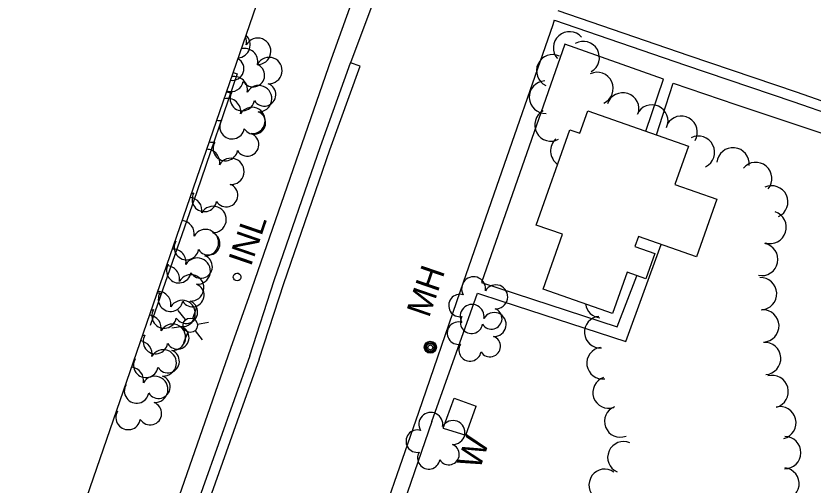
# Model space of a CAD drawing. Extents: x 189384 to 193282, y 256970 to 260388.
# Drawn here: x 190383.3 to 190581.3, y 258710.5 to 258826.9 of the extents above; entities that cross this region are included whole.
import ezdxf

# ---------------------------------------------------------------- set-up
doc = ezdxf.new("R2010")
doc.units = 0
for name, color, linetype in [('E_DRN_Grate', 7, 'Continuous'), ('E_DWY', 7, 'Continuous'), ('E_LAND_Vegetation', 7, 'Continuous'), ('E_MAP_Limits', 7, 'Continuous'), ('E_MISCPROP', 7, 'Continuous'), ('E_MISCPROP_HvyLine', 7, 'Continuous'), ('E_MISCPROP_Railing', 7, 'Continuous'), ('E_PATH_Sidewalk', 7, 'Continuous'), ('E_RDWY', 7, 'Continuous')]:
    doc.layers.add(name, color=color, linetype=linetype)

# ---------------------------------------------------------------- blocks, each defined once
blk = doc.blocks.new('INL_2')
at = {"layer": 'E_MISCPROP_Railing'}
blk.add_text('INL', height=6, rotation=359.9999, dxfattribs=at).set_placement((-5.79, -2.75))
blk = doc.blocks.new('LTP_12')
at = {"layer": 'E_MISCPROP'}
for p, q in [((-0.88, 1.57), (-2.2, 4.11)), ((0.99, 1.56), (2.49, 4.02)), ((-1.8, 0.07), (-4.66, 0.15)), ((-0.96, -1.57), (-2.46, -3.98)), ((0.83, -1.62), (2.2, -4.01)), ((1.8, -0.03), (4.58, -0.1))]:
    blk.add_line(p, q, dxfattribs=at)
blk.add_circle((0, 0), 1.8, dxfattribs=at)
blk = doc.blocks.new('MHO_5')
at = {"layer": 'E_DRN_Grate'}
for centre, radius in [((0.04, -0.06), 1.5), ((0.04, -0.06), 1.22), ((0.04, -0.07), 0.968), ((0.01, -0.08), 0.605)]:
    blk.add_circle(centre, radius, dxfattribs=at)
blk = doc.blocks.new('WAL_7')
at = {"layer": 'E_MISCPROP_Railing'}
blk.add_text('W', height=6, rotation=0.0001, dxfattribs=at).set_placement((-2.27, -3.34))
blk = doc.blocks.new('TREE_11')
at = {"layer": 'E_LAND_Vegetation'}
for centre, radius, start, end in [((-1.47, 4.28), 2.78, 1.3946, 209.1676), ((3.57, 2.42), 2.97, 278.4237, 139.6576), ((-4.47, 0.2), 2.78, 78.0716, 279.0827), ((3.46, -3.43), 2.97, 196.0745, 79.0478), ((-2.01, -4.2), 2.61, 140.7798, 358.7124)]:
    blk.add_arc(centre, radius, start, end, dxfattribs=at)

msp = doc.modelspace()

# ---------------------------------------------------------------- linework, layer by layer
at = {"layer": 'E_DWY'}
msp.add_lwpolyline([(190437.28, 258812.87), (190438.3, 258812.51), (190428.25, 258783.25), (190416.64, 258750.06)], dxfattribs=at)
at = {"layer": 'E_LAND_Vegetation'}
for centre, radius, start, end in [((190438.25, 258819.76), 3.27, 274.9201, 47.0406), ((190437.34, 258820.36), 3.27, 349.4611, 24.2947), ((190443.39, 258818.15), 3.27, 267.1119, 150.0852), ((190520.83, 258818.98), 4.02, 41.5431, 221.5278), ((190524.24, 258816.6), 4.02, 299.2194, 119.2041), ((190440.13, 258815.58), 3.27, 349.4611, 104.6274), ((190516.66, 258813.31), 4.02, 64.5499, 244.5346), ((190437.09, 258813.8), 2.87, 260.6064, 61.3543), ((190446.18, 258813.37), 3.27, 267.1119, 150.0852), ((190442.23, 258812.19), 2.87, 211.8171, 69.7497), ((190437.59, 258808.6), 3.27, 349.4611, 102.0227), ((190527.66, 258808.92), 4.02, 294.5945, 114.5792), ((190436.78, 258811.2), 3.06, 249.6819, 350.12), ((190443.64, 258806.39), 3.27, 267.1119, 150.0852), ((190445.02, 258807.41), 2.87, 211.8171, 69.7497), ((190514.84, 258806.76), 4.02, 92.4972, 272.4819), ((190436.39, 258811), 3.05, 255.2097, 280.205), ((190439.56, 258806.42), 3.06, 149.109, 350.12), ((190534.07, 258803.84), 4.02, 341.8243, 161.809), ((190435.91, 258803.18), 3.27, 349.4611, 105.8454), ((190441.96, 258800.97), 3.27, 267.1119, 150.0852), ((190516.21, 258799.85), 4.02, 118.6237, 298.6084), ((190541.28, 258800.84), 4.02, 336.0452, 156.0299), ((190442.48, 258800.43), 2.87, 211.8171, 69.7497), ((190548.56, 258798.04), 4.02, 329.8882, 149.8729), ((190433.85, 258804.02), 3.05, 257.5768, 280.205), ((190437.02, 258799.44), 3.06, 149.109, 350.12), ((190440.8, 258795.01), 2.87, 211.8171, 69.7497), ((190432.18, 258798.6), 3.05, 254.1293, 280.205), ((190435.35, 258794.02), 3.06, 149.109, 350.12), ((190520.14, 258793.43), 4.02, 132.1523, 235.6774), ((190552.84, 258793.08), 4.02, 296.6675, 116.6522), ((190430.69, 258790.56), 3.27, 349.4611, 89.6597), ((190561.45, 258790.2), 4.02, 354.508, 174.4927), ((190436.74, 258788.35), 3.27, 267.1119, 150.0852), ((190567.1, 258786.57), 4.02, 320.161, 140.1457), ((190435.59, 258782.39), 2.87, 211.8171, 69.7497), ((190571.06, 258780.75), 4.02, 295.2791, 115.2638), ((190426.26, 258778.62), 3.27, 349.4611, 84.1682), ((190426.96, 258785.98), 3.05, 269.8933, 280.205), ((190430.13, 258781.4), 3.06, 149.109, 350.12), ((190432.31, 258776.41), 3.27, 267.1119, 150.0852), ((190570.67, 258774.45), 4.02, 252.3944, 72.3791), ((190424.36, 258772.86), 3.27, 349.4611, 85.5461), ((190430.41, 258770.66), 3.27, 267.1119, 150.0852), ((190431.15, 258770.45), 2.87, 211.8171, 69.7497), ((190425.69, 258769.46), 3.06, 149.109, 350.12), ((190422.52, 258774.03), 3.05, 275.9913, 280.205), ((190568.57, 258766.48), 4.02, 258.3214, 78.306), ((190422.31, 258765.79), 3.27, 349.4611, 92.3949), ((190428.36, 258763.58), 3.27, 267.1119, 150.0852), ((190429.25, 258764.69), 2.87, 211.8171, 69.7497), ((190423.79, 258763.7), 3.06, 149.109, 350.12), ((190420.71, 258761.63), 3.27, 349.4611, 89.5112), ((190420.62, 258768.28), 3.05, 274.4204, 280.205), ((190426.76, 258759.42), 3.27, 267.1119, 150.0852), ((190568.28, 258757.98), 4.02, 272.7769, 92.7616), ((190427.2, 258757.62), 2.87, 211.8171, 69.7497), ((190418.58, 258761.21), 3.05, 267.0086, 280.205), ((190418.57, 258755.28), 3.27, 349.4611, 90.2751), ((190421.75, 258756.63), 3.06, 149.109, 350.12), ((190424.62, 258753.07), 3.27, 267.1119, 150.0852), ((190425.6, 258753.46), 2.87, 211.8171, 69.7497), ((190416.98, 258757.05), 3.05, 270.0528, 280.205), ((190420.15, 258752.47), 3.06, 149.109, 350.12), ((190528.69, 258755.94), 3.92, 187.4333, 265.8223), ((190568.85, 258749.99), 4.02, 272.1291, 92.1138), ((190416.17, 258749.38), 3.27, 349.4611, 84.0272), ((190528.45, 258748.44), 3.92, 94.5735, 274.5582), ((190422.22, 258747.17), 3.27, 267.1119, 150.0852), ((190423.46, 258747.1), 2.87, 211.8171, 69.7497), ((190413.87, 258743.02), 3.27, 349.4611, 82.2034), ((190414.83, 258750.69), 3.05, 269.2359, 280.205), ((190418, 258746.12), 3.06, 149.109, 350.12), ((190569.3, 258741.9), 4.02, 274.0311, 94.0158), ((190419.92, 258740.81), 3.27, 267.1119, 150.0852), ((190421.06, 258741.2), 2.87, 211.8171, 69.7497), ((190529.05, 258740.74), 3.92, 98.0905, 278.0752), ((190415.6, 258740.22), 3.06, 149.109, 350.12), ((190412.44, 258744.79), 3.05, 276.1537, 280.205), ((190411.77, 258736.45), 3.27, 349.4611, 85.0277), ((190417.82, 258734.24), 3.27, 267.1119, 150.0852), ((190418.76, 258734.85), 2.87, 211.8171, 69.7497), ((190530.54, 258733.47), 3.92, 108.8594, 288.8441), ((190571.16, 258733.69), 4.02, 285.353, 105.3377), ((190413.31, 258733.86), 3.06, 149.109, 350.12), ((190410.14, 258738.44), 3.05, 278.2825, 280.205), ((190416.66, 258728.28), 2.87, 211.8171, 69.7497), ((190411.21, 258727.29), 3.06, 149.109, 350.12), ((190408.04, 258731.87), 3.05, 275.0081, 280.205), ((190533.45, 258726.29), 3.92, 111.3205, 291.3052), ((190573.1, 258725.95), 4.02, 283.8724, 103.8571), ((190574.29, 258718.55), 4.02, 269.204, 89.1886), ((190534.23, 258717.35), 3.92, 65.9456, 245.9303), ((190529.59, 258710.54), 3.92, 54.3628, 234.3475), ((190573.85, 258710.77), 4.02, 263.041, 83.0257)]:
    msp.add_arc(centre, radius, start, end, dxfattribs=at)
at = {"layer": 'E_MAP_Limits'}
msp.add_lwpolyline([(190400.94, 258707.45), (190457.96, 258872.88)], dxfattribs=at)
at = {"layer": 'E_MISCPROP_HvyLine'}
msp.add_lwpolyline([(190525.39, 258803.4), (190550.36, 258794.62), (190547, 258785.08), (190557.4, 258781.43), (190552.38, 258767.14), (190537.94, 258772.21), (190537.07, 258769.72), (190542.02, 258767.98), (190539.8, 258761.64), (190535.12, 258763.29), (190531.53, 258753.07), (190514.33, 258759.12), (190519.11, 258772.72), (190512.57, 258775.02), (190520.89, 258798.68), (190523.42, 258797.79)], close=True, dxfattribs=at)
at = {"layer": 'E_MISCPROP_Railing'}
for points in [[(190489.49, 258724.63), (190492.16, 258732.03), (190497.68, 258730.04)], [(190489.49, 258724.63), (190495.08, 258722.85), (190497.68, 258730.04)]]:
    msp.add_lwpolyline(points, dxfattribs=at)
msp.add_ellipse((190438.27, 258762.13), major_axis=(-0.908, 0.299), ratio=0.999792, dxfattribs=at)
at = {"layer": 'E_PATH_Sidewalk'}
for points in [[(190447.18, 258841.59), (190468.1, 258834.24), (190461.64, 258816.22), (190441.14, 258757.22), (190436.59, 258744.35), (190421.31, 258700.47)], [(190539.82, 258798.33), (190544.16, 258811.25), (190544.15, 258811.23), (190519.66, 258819.88), (190498.95, 258760.8), (190532.71, 258749.79), (190537.54, 258762.44)], [(190542.43, 258797.41), (190544.72, 258804.59), (190546.6, 258810.25), (190562.16, 258804.98), (190584.72, 258797.43)], [(190486.64, 258726.28), (190497.97, 258758.11), (190504.03, 258756.15), (190534.79, 258746.1), (190543.64, 258770.21)], [(190486.64, 258726.28), (190473.61, 258688.57)]]:
    msp.add_lwpolyline(points, dxfattribs=at)
at = {"layer": 'E_RDWY'}
for points in [[(190450.5, 258851.22), (190472.19, 258843.7), (190474.02, 258842.86), (190474.53, 258842.35), (190474.82, 258841.87), (190474.94, 258841.39), (190475.31, 258840.22), (190475.32, 258839.68), (190475.2, 258839.12), (190472.95, 258832.78), (190466.45, 258815.28)], [(190517.92, 258828.27), (190550.43, 258817.07), (190577.1, 258808.05), (190598.18, 258800.75), (190616.38, 258794.51), (190642.44, 258785.51), (190649.41, 258783.07), (190686.16, 258770.53), (190696.24, 258766.91)], [(190470.58, 258691.68), (190483.37, 258728.62), (190493.78, 258758.71), (190502.09, 258782.76), (190516.78, 258824.81), (190517.11, 258825.92)], [(190517.1, 258825.9), (190549.63, 258814.7), (190576.29, 258805.69), (190597.36, 258798.39), (190615.57, 258792.15), (190641.62, 258783.15), (190648.59, 258780.71), (190685.33, 258768.17), (190695.4, 258764.56)], [(190441.39, 258742.52), (190447.47, 258761.28), (190458.96, 258794.54), (190466.45, 258815.28)], [(190443.77, 258741.74), (190449.84, 258760.48), (190461.31, 258793.7), (190468.8, 258814.43), (190466.45, 258815.28)], [(190441.39, 258742.52), (190425.87, 258698.91), (190422.78, 258690.21), (190396.55, 258614.58), (190383.33, 258576.48)], [(190443.77, 258741.74), (190428.24, 258698.1), (190425.13, 258689.38), (190398.92, 258613.76), (190385.7, 258575.66), (190383.33, 258576.48)]]:
    msp.add_lwpolyline(points, dxfattribs=at)

# ---------------------------------------------------------------- block references
at = {"layer": 'E_DRN_Grate', "rotation": 71.0373537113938}
msp.add_blockref('MHO_5', (190486.19, 258744.67), dxfattribs=at)
at = {"layer": 'E_LAND_Vegetation'}
for p, rotation in [((190498.14, 258755.05), 71.03735349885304), ((190497.76, 258748.18), 71.03735350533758), ((190487.52, 258721.38), 71.03735368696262)]:
    msp.add_blockref('TREE_11', p, dxfattribs=dict(at, rotation=rotation))
at = {"layer": 'E_MISCPROP', "rotation": 71.03735477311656}
msp.add_blockref('LTP_12', (190426.64, 258750.15), dxfattribs=at)
at = {"layer": 'E_MISCPROP_Railing'}
for name, p, rotation in [('INL_2', (190440.95, 258770.9), 71.0373545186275), ('WAL_7', (190496.07, 258717.31), 71.03735353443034)]:
    msp.add_blockref(name, p, dxfattribs=dict(at, rotation=rotation))

# ---------------------------------------------------------------- texts
at = {"layer": 'E_DRN_Grate'}
msp.add_text('MH', height=6, rotation=71.0374, dxfattribs=at).set_placement((190485.92, 258751.81))

doc.saveas('drawing.dxf')
